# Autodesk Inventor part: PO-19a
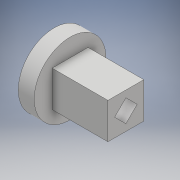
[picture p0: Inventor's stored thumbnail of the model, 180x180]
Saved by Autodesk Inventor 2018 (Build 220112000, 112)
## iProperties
Created: 2020-01
Part Number: PO-19a
Material: Générique
Document SubType Name: Modeling
Designer: TJ
Density: 1 g/cm^3
Appearance: Par défaut
Author: TJ
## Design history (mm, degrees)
sketch "Esquisse1"
  geometry: C1 r 18 at (0, 0); 1 further point
  constraints: 1 centre point, 1 coincident
  dimensions: "d0" = 36 diameter of C1
extrude "Extrusion1" new body sketch "Esquisse1" distance "d1" = 8; taper "d2" = 0 deg
sketch "Esquisse2"
  geometry: L1 (-9, 9)-(9, 9); L2 (9, 9)-(9, -9); L3 (9, -9)-(-9, -9); L4 (-9, -9)-(-9, 9); L5 (-9, 9)-(9, -9); L6 (9, 9)-(-9, -9); 1 further point
  constraints: 12 end point, 2 midpoint, 2 parallel, 1 horizontal, 1 perpendicular
  dimensions: "d3" = 18 distance of L1.start L1.end; "d4" = 18 distance of L3.end L1.start (= d3)
extrude "Extrusion2" join sketch "Esquisse2" distance "d5" = 28; taper "d6" = 0 deg
sketch "Esquisse3"
  geometry: L1 (0, 5.657)-(5.657, 0); L2 (5.657, 0)-(0, -5.657); L3 (0, -5.657)-(-5.657, 0); L4 (-5.657, 0)-(0, 5.657); L5 (-9, -9)-(9, -9) reference; 1 further point
  constraints: 8 end point, 2 perpendicular, 1 parallel
  dimensions: "d7" = 45 deg angle of L5 L3; "d8" = 8 distance of L3.end L1.start; "d9" = 8 distance of L1.start L1.end; "d16" = 11.31371 distance of L1.start L2.end (derived); "d17" = 5.65685 distance of L3.end point (0, 0) (= 0.5 x d16); "d18" = 5.65685 distance of L2.end point (0, 0) (= 0.5 x d16)
extrude "Extrusion3" cut sketch "Esquisse3" extent not by distance; stored distance "d13" = 28; taper "d14" = 0 deg
node "Solide1"
